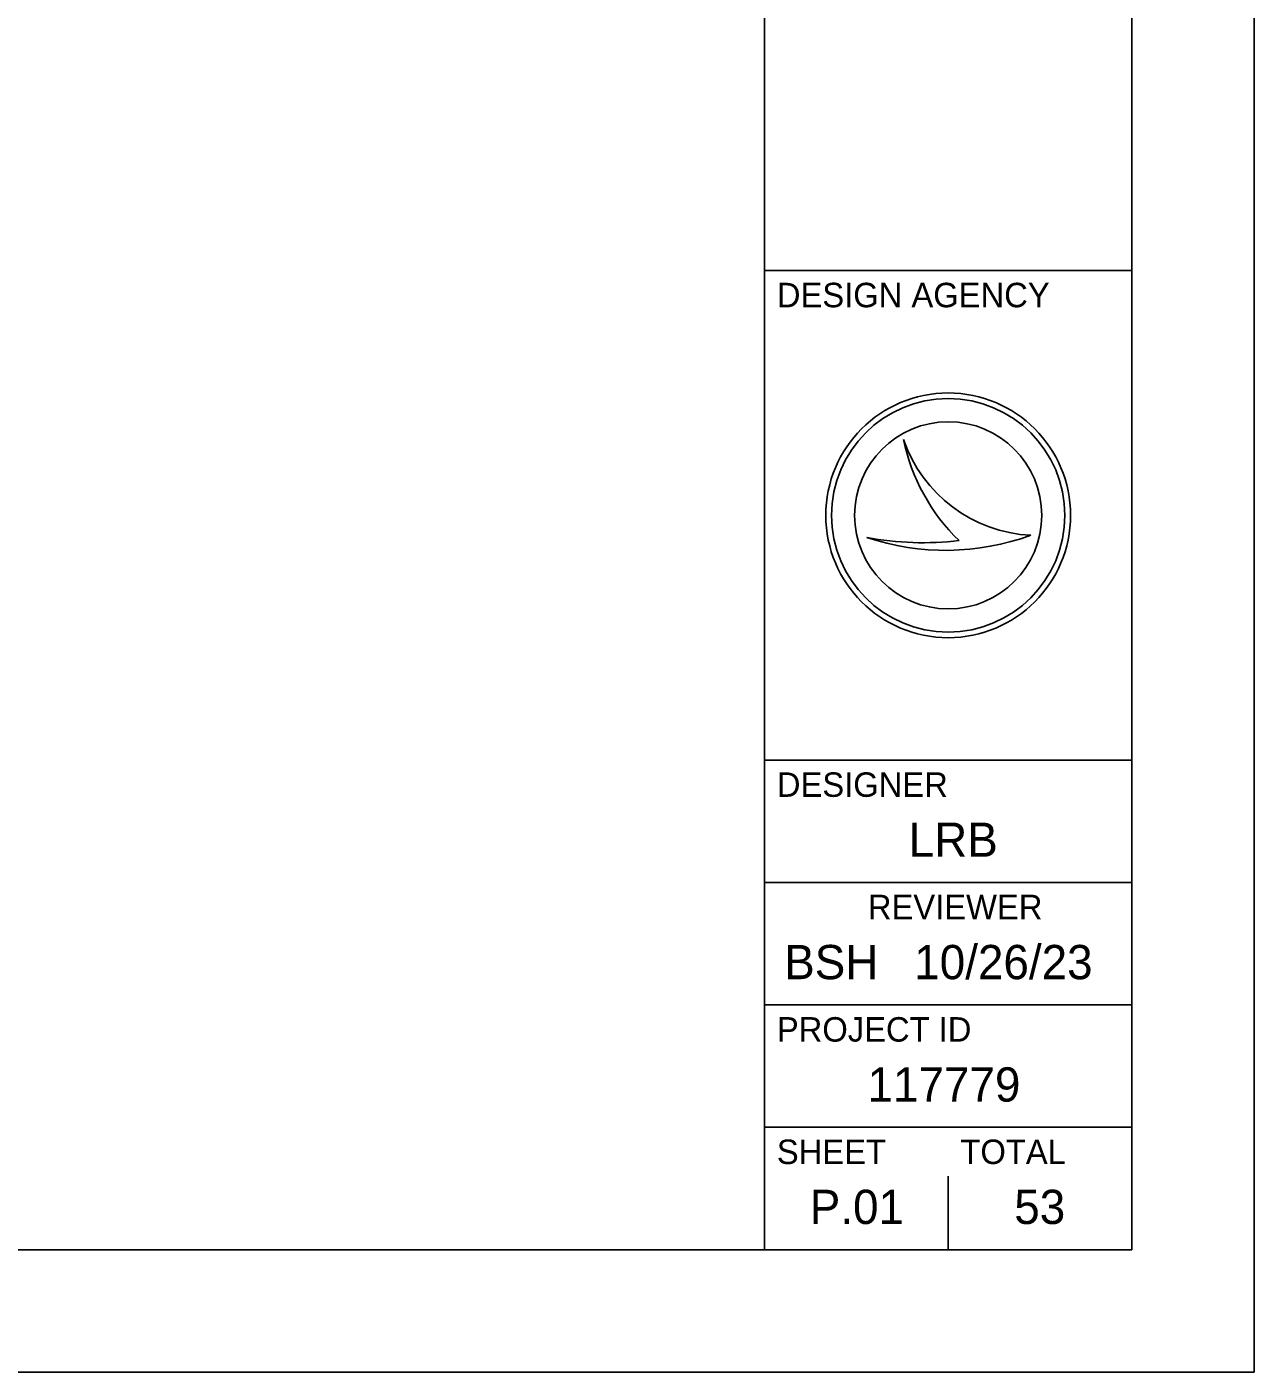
# Model space of a CAD drawing. Extents: x -3.6 to 34, y 0 to 32.8.
# Drawn here: x 28.99 to 34, y 0 to 5.5 of the extents above; entities that cross this region are included whole.
import ezdxf

# ---------------------------------------------------------------- set-up
doc = ezdxf.new("R2010")
doc.units = 0
for name, color, linetype in [('SH_Border', 7, 'Continuous'), ('SH_Cut_Line', 7, 'Continuous'), ('SH_Data', 7, 'Continuous')]:
    doc.layers.add(name, color=color, linetype=linetype)

msp = doc.modelspace()

# ---------------------------------------------------------------- linework, layer by layer
at = {"layer": 'SH_Border'}
for p, q in [((32, 0.5), (32, 21.5)), ((32, 4.5), (33.5, 4.5)), ((32, 2.5), (33.5, 2.5)), ((32, 2), (33.5, 2)), ((32, 1.5), (33.5, 1.5)), ((32, 1), (33.5, 1))]:
    msp.add_line(p, q, dxfattribs=at)
msp.add_lwpolyline([(1.5, 21.5), (33.5, 21.5), (33.5, 0.5), (1.5, 0.5)], close=True, dxfattribs=at)
at = {"layer": 'SH_Cut_Line'}
msp.add_lwpolyline([(0, 0), (34, 0), (34, 22), (0, 22)], close=True, dxfattribs=at)
at = {"layer": 'SH_Data'}
for p, q in [((32.5674, 3.8096), (32.5675, 3.8096)), ((32.75, 3.5), (32.75, 3.5)), ((32.4172, 3.4095), (32.4172, 3.4095)), ((33.0873, 3.4185), (33.0873, 3.4185)), ((32.75, 0.5), (32.75, 0.8)), ((32.375, 0.675), (32.375, 0.675))]:
    msp.add_line(p, q, dxfattribs=at)
for radius in [0.5, 0.4768, 0.4768, 0.3822]:
    msp.add_circle((32.75, 3.5), radius, dxfattribs=at)
for centre, radius, start, end in [((33.1159, 3.9976), 0.5798, 198.9257, 198.9319), ((33.3467, 3.9701), 0.7956, 191.6379, 191.6421), ((33.1159, 3.9976), 0.5798, 198.9319, 267.1657), ((33.3467, 3.9701), 0.7956, 191.6421, 226.0947), ((32.7394, 4.37), 1.0131, 251.4576, 290.0832), ((32.648, 4.6543), 1.2661, 259.4964, 259.4995), ((32.7394, 4.37), 1.0131, 251.4527, 251.4576), ((32.648, 4.6543), 1.2661, 259.4995, 276.6672)]:
    msp.add_arc(centre, radius, start, end, dxfattribs=at)

# ---------------------------------------------------------------- texts
for s, height, p in [('DESIGN AGENCY', 0.1, (32.05, 4.35)), ('DESIGNER', 0.1, (32.05, 2.35)), ('LRB', 0.14, (32.5886, 2.105)), ('REVIEWER', 0.1, (32.4218, 1.85)), ('BSH', 0.14, (32.0798, 1.605)), ('10/26/23', 0.14, (32.6113, 1.605)), ('PROJECT ID', 0.1, (32.05, 1.35)), ('117779', 0.14, (32.4204, 1.105)), ('SHEET', 0.1, (32.05, 0.85)), ('TOTAL', 0.1, (32.8, 0.85)), ('P.01', 0.14, (32.1844, 0.605)), ('53', 0.14, (33.02, 0.605))]:
    msp.add_text(s, height=height, dxfattribs=at).set_placement(p)

doc.saveas('drawing.dxf')
